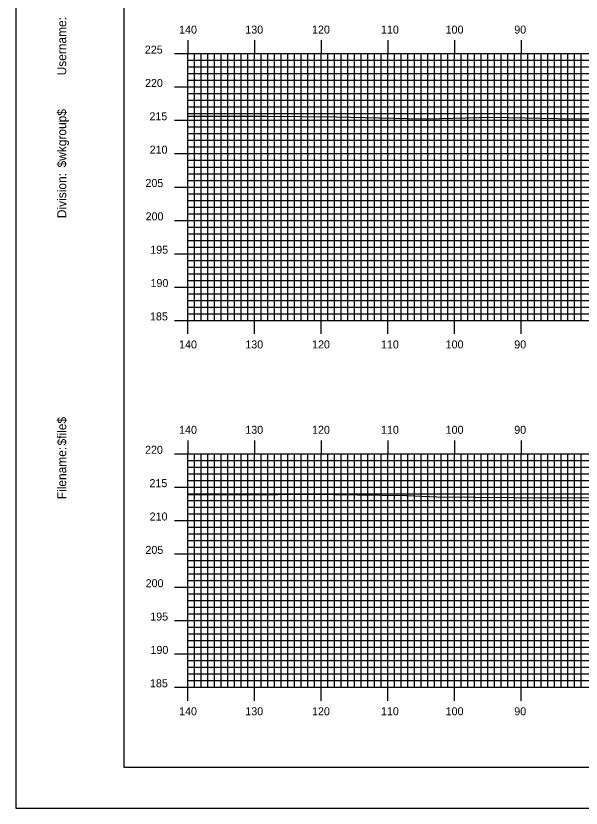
# Model space of a CAD drawing. Extents: x 1800355 to 1800699, y 442591 to 442811.
# Drawn here: x 1800355.2 to 1800440, y 442590.5 to 442709.3 of the extents above; entities that cross this region are included whole.
import ezdxf

# ---------------------------------------------------------------- set-up
doc = ezdxf.new("R2010")
doc.units = 0
for name, color, linetype in [('BORDER', 7, 'Continuous'), ('H_V ANNOTATION', 7, 'Continuous'), ('MAJOR', 7, 'Continuous'), ('MINOR', 7, 'Continuous'), ('PLOT BOUNDARY', 7, 'Continuous'), ('S_Roadway_Centerline', 7, 'Continuous')]:
    doc.layers.add(name, color=color, linetype=linetype)

msp = doc.modelspace()

# ---------------------------------------------------------------- linework, layer by layer
at = {"layer": 'BORDER'}
msp.add_lwpolyline([(1800371.44, 442596.67), (1800691.44, 442596.67), (1800691.44, 442806.67), (1800371.44, 442806.67)], close=True, dxfattribs=at)
at = {"layer": 'MAJOR'}
for p, q in [((1800381.04, 442705.67), (1800381.04, 442703.67)), ((1800391.04, 442705.67), (1800391.04, 442703.67)), ((1800401.04, 442705.67), (1800401.04, 442703.67)), ((1800411.04, 442705.67), (1800411.04, 442703.67)), ((1800421.04, 442705.67), (1800421.04, 442703.67)), ((1800431.04, 442705.67), (1800431.04, 442703.67)), ((1800379.03, 442703.67), (1800381.04, 442703.67)), ((1800381.04, 442703.67), (1800661.04, 442703.67)), ((1800381.04, 442663.67), (1800381.04, 442703.67)), ((1800381.04, 442663.67), (1800381.04, 442703.67)), ((1800381.04, 442703.67), (1800661.04, 442703.67)), ((1800391.04, 442663.67), (1800391.04, 442703.67)), ((1800401.04, 442663.67), (1800401.04, 442703.67)), ((1800411.04, 442663.67), (1800411.04, 442703.67)), ((1800421.04, 442663.67), (1800421.04, 442703.67)), ((1800431.04, 442663.67), (1800431.04, 442703.67)), ((1800379.03, 442698.67), (1800381.04, 442698.67)), ((1800381.04, 442698.67), (1800661.04, 442698.67)), ((1800379.03, 442693.67), (1800381.04, 442693.67)), ((1800381.04, 442693.67), (1800661.04, 442693.67)), ((1800379.03, 442688.67), (1800381.04, 442688.67)), ((1800381.04, 442688.67), (1800661.04, 442688.67)), ((1800379.03, 442683.67), (1800381.04, 442683.67)), ((1800381.04, 442683.67), (1800661.04, 442683.67)), ((1800379.03, 442678.67), (1800381.04, 442678.67)), ((1800381.04, 442678.67), (1800661.04, 442678.67)), ((1800379.03, 442673.67), (1800381.04, 442673.67)), ((1800381.04, 442673.67), (1800661.04, 442673.67)), ((1800379.03, 442668.67), (1800381.04, 442668.67)), ((1800381.04, 442668.67), (1800661.04, 442668.67)), ((1800379.03, 442663.67), (1800381.04, 442663.67)), ((1800381.04, 442663.67), (1800661.04, 442663.67)), ((1800381.04, 442663.67), (1800661.04, 442663.67)), ((1800381.04, 442661.66), (1800381.04, 442663.67)), ((1800391.04, 442661.66), (1800391.04, 442663.67)), ((1800401.04, 442661.66), (1800401.04, 442663.67)), ((1800411.04, 442661.66), (1800411.04, 442663.67)), ((1800421.04, 442661.66), (1800421.04, 442663.67)), ((1800431.04, 442661.66), (1800431.04, 442663.67)), ((1800381.04, 442645.67), (1800381.04, 442643.67)), ((1800391.04, 442645.67), (1800391.04, 442643.67)), ((1800401.04, 442645.67), (1800401.04, 442643.67)), ((1800411.04, 442645.67), (1800411.04, 442643.67)), ((1800421.04, 442645.67), (1800421.04, 442643.67)), ((1800431.04, 442645.67), (1800431.04, 442643.67)), ((1800379.03, 442643.67), (1800381.04, 442643.67)), ((1800381.04, 442643.67), (1800661.04, 442643.67)), ((1800381.04, 442608.67), (1800381.04, 442643.67)), ((1800381.04, 442608.67), (1800381.04, 442643.67)), ((1800381.04, 442643.67), (1800661.04, 442643.67)), ((1800391.04, 442608.67), (1800391.04, 442643.67)), ((1800401.04, 442608.67), (1800401.04, 442643.67)), ((1800411.04, 442608.67), (1800411.04, 442643.67)), ((1800421.04, 442608.67), (1800421.04, 442643.67)), ((1800431.04, 442608.67), (1800431.04, 442643.67)), ((1800379.03, 442638.67), (1800381.04, 442638.67)), ((1800381.04, 442638.67), (1800661.04, 442638.67)), ((1800379.03, 442633.67), (1800381.04, 442633.67)), ((1800381.04, 442633.67), (1800661.04, 442633.67)), ((1800379.03, 442628.67), (1800381.04, 442628.67)), ((1800381.04, 442628.67), (1800661.04, 442628.67)), ((1800379.03, 442623.67), (1800381.04, 442623.67)), ((1800381.04, 442623.67), (1800661.04, 442623.67)), ((1800379.03, 442618.67), (1800381.04, 442618.67)), ((1800381.04, 442618.67), (1800661.04, 442618.67)), ((1800379.03, 442613.67), (1800381.04, 442613.67)), ((1800381.04, 442613.67), (1800661.04, 442613.67)), ((1800379.03, 442608.67), (1800381.04, 442608.67)), ((1800381.04, 442608.67), (1800661.04, 442608.67)), ((1800381.04, 442608.67), (1800661.04, 442608.67)), ((1800381.04, 442606.66), (1800381.04, 442608.67)), ((1800391.04, 442606.66), (1800391.04, 442608.67)), ((1800401.04, 442606.66), (1800401.04, 442608.67)), ((1800411.04, 442606.66), (1800411.04, 442608.67)), ((1800421.04, 442606.66), (1800421.04, 442608.67)), ((1800431.04, 442606.66), (1800431.04, 442608.67))]:
    msp.add_line(p, q, dxfattribs=at)
at = {"layer": 'MINOR'}
for p, q in [((1800381.04, 442702.67), (1800661.04, 442702.67)), ((1800381.04, 442702.67), (1800383.04, 442702.67)), ((1800382.04, 442663.67), (1800382.04, 442703.67)), ((1800383.04, 442663.67), (1800383.04, 442703.67)), ((1800384.04, 442663.67), (1800384.04, 442703.67)), ((1800385.04, 442663.67), (1800385.04, 442703.67)), ((1800386.04, 442663.67), (1800386.04, 442703.67)), ((1800387.04, 442663.67), (1800387.04, 442703.67)), ((1800388.04, 442663.67), (1800388.04, 442703.67)), ((1800389.04, 442663.67), (1800389.04, 442703.67)), ((1800390.04, 442663.67), (1800390.04, 442703.67)), ((1800392.04, 442663.67), (1800392.04, 442703.67)), ((1800393.04, 442663.67), (1800393.04, 442703.67)), ((1800394.04, 442663.67), (1800394.04, 442703.67)), ((1800395.04, 442663.67), (1800395.04, 442703.67)), ((1800396.04, 442663.67), (1800396.04, 442703.67)), ((1800397.04, 442663.67), (1800397.04, 442703.67)), ((1800398.04, 442663.67), (1800398.04, 442703.67)), ((1800399.04, 442663.67), (1800399.04, 442703.67)), ((1800400.04, 442663.67), (1800400.04, 442703.67)), ((1800402.04, 442663.67), (1800402.04, 442703.67)), ((1800403.04, 442663.67), (1800403.04, 442703.67)), ((1800404.04, 442663.67), (1800404.04, 442703.67)), ((1800405.04, 442663.67), (1800405.04, 442703.67)), ((1800406.04, 442663.67), (1800406.04, 442703.67)), ((1800407.04, 442663.67), (1800407.04, 442703.67)), ((1800408.04, 442663.67), (1800408.04, 442703.67)), ((1800409.04, 442663.67), (1800409.04, 442703.67)), ((1800410.04, 442663.67), (1800410.04, 442703.67)), ((1800412.04, 442663.67), (1800412.04, 442703.67)), ((1800413.04, 442663.67), (1800413.04, 442703.67)), ((1800414.04, 442663.67), (1800414.04, 442703.67)), ((1800415.04, 442663.67), (1800415.04, 442703.67)), ((1800416.04, 442663.67), (1800416.04, 442703.67)), ((1800417.04, 442663.67), (1800417.04, 442703.67)), ((1800418.04, 442663.67), (1800418.04, 442703.67)), ((1800419.04, 442663.67), (1800419.04, 442703.67)), ((1800420.04, 442663.67), (1800420.04, 442703.67)), ((1800422.04, 442663.67), (1800422.04, 442703.67)), ((1800423.04, 442663.67), (1800423.04, 442703.67)), ((1800424.04, 442663.67), (1800424.04, 442703.67)), ((1800425.04, 442663.67), (1800425.04, 442703.67)), ((1800426.04, 442663.67), (1800426.04, 442703.67)), ((1800427.04, 442663.67), (1800427.04, 442703.67)), ((1800428.04, 442663.67), (1800428.04, 442703.67)), ((1800429.04, 442663.67), (1800429.04, 442703.67)), ((1800430.04, 442663.67), (1800430.04, 442703.67)), ((1800432.04, 442663.67), (1800432.04, 442703.67)), ((1800433.04, 442663.67), (1800433.04, 442703.67)), ((1800434.04, 442663.67), (1800434.04, 442703.67)), ((1800435.04, 442663.67), (1800435.04, 442703.67)), ((1800436.04, 442663.67), (1800436.04, 442703.67)), ((1800437.04, 442663.67), (1800437.04, 442703.67)), ((1800438.04, 442663.67), (1800438.04, 442703.67)), ((1800439.04, 442663.67), (1800439.04, 442703.67)), ((1800440.04, 442663.67), (1800440.04, 442703.67)), ((1800381.04, 442701.67), (1800661.04, 442701.67)), ((1800381.04, 442701.67), (1800383.04, 442701.67)), ((1800381.04, 442700.67), (1800661.04, 442700.67)), ((1800381.04, 442700.67), (1800383.04, 442700.67)), ((1800381.04, 442699.67), (1800661.04, 442699.67)), ((1800381.04, 442699.67), (1800383.04, 442699.67)), ((1800381.04, 442697.67), (1800661.04, 442697.67)), ((1800381.04, 442697.67), (1800383.04, 442697.67)), ((1800381.04, 442696.67), (1800661.04, 442696.67)), ((1800381.04, 442696.67), (1800383.04, 442696.67)), ((1800381.04, 442695.67), (1800661.04, 442695.67)), ((1800381.04, 442695.67), (1800383.04, 442695.67)), ((1800381.04, 442694.67), (1800661.04, 442694.67)), ((1800381.04, 442694.67), (1800383.04, 442694.67)), ((1800381.04, 442692.67), (1800661.04, 442692.67)), ((1800381.04, 442692.67), (1800383.04, 442692.67)), ((1800381.04, 442691.67), (1800661.04, 442691.67)), ((1800381.04, 442691.67), (1800383.04, 442691.67)), ((1800381.04, 442690.67), (1800661.04, 442690.67)), ((1800381.04, 442690.67), (1800383.04, 442690.67)), ((1800381.04, 442689.67), (1800661.04, 442689.67)), ((1800381.04, 442689.67), (1800383.04, 442689.67)), ((1800381.04, 442687.67), (1800661.04, 442687.67)), ((1800381.04, 442687.67), (1800383.04, 442687.67)), ((1800381.04, 442686.67), (1800661.04, 442686.67)), ((1800381.04, 442686.67), (1800383.04, 442686.67)), ((1800381.04, 442685.67), (1800661.04, 442685.67)), ((1800381.04, 442685.67), (1800383.04, 442685.67)), ((1800381.04, 442684.67), (1800661.04, 442684.67)), ((1800381.04, 442684.67), (1800383.04, 442684.67)), ((1800381.04, 442682.67), (1800661.04, 442682.67)), ((1800381.04, 442682.67), (1800383.04, 442682.67)), ((1800381.04, 442681.67), (1800661.04, 442681.67)), ((1800381.04, 442681.67), (1800383.04, 442681.67)), ((1800381.04, 442680.67), (1800661.04, 442680.67)), ((1800381.04, 442680.67), (1800383.04, 442680.67)), ((1800381.04, 442679.67), (1800661.04, 442679.67)), ((1800381.04, 442679.67), (1800383.04, 442679.67)), ((1800381.04, 442677.67), (1800661.04, 442677.67)), ((1800381.04, 442677.67), (1800383.04, 442677.67)), ((1800381.04, 442676.67), (1800661.04, 442676.67)), ((1800381.04, 442676.67), (1800383.04, 442676.67)), ((1800381.04, 442675.67), (1800661.04, 442675.67)), ((1800381.04, 442675.67), (1800383.04, 442675.67)), ((1800381.04, 442674.67), (1800661.04, 442674.67)), ((1800381.04, 442674.67), (1800383.04, 442674.67)), ((1800381.04, 442672.67), (1800661.04, 442672.67)), ((1800381.04, 442672.67), (1800383.04, 442672.67)), ((1800381.04, 442671.67), (1800661.04, 442671.67)), ((1800381.04, 442671.67), (1800383.04, 442671.67)), ((1800381.04, 442670.67), (1800661.04, 442670.67)), ((1800381.04, 442670.67), (1800383.04, 442670.67)), ((1800381.04, 442669.67), (1800661.04, 442669.67)), ((1800381.04, 442669.67), (1800383.04, 442669.67)), ((1800381.04, 442667.67), (1800661.04, 442667.67)), ((1800381.04, 442667.67), (1800383.04, 442667.67)), ((1800381.04, 442666.67), (1800661.04, 442666.67)), ((1800381.04, 442666.67), (1800383.04, 442666.67)), ((1800381.04, 442665.67), (1800661.04, 442665.67)), ((1800381.04, 442665.67), (1800383.04, 442665.67)), ((1800381.04, 442664.67), (1800661.04, 442664.67)), ((1800381.04, 442664.67), (1800383.04, 442664.67)), ((1800382.04, 442608.67), (1800382.04, 442643.67)), ((1800383.04, 442608.67), (1800383.04, 442643.67)), ((1800384.04, 442608.67), (1800384.04, 442643.67)), ((1800385.04, 442608.67), (1800385.04, 442643.67)), ((1800386.04, 442608.67), (1800386.04, 442643.67)), ((1800387.04, 442608.67), (1800387.04, 442643.67)), ((1800388.04, 442608.67), (1800388.04, 442643.67)), ((1800389.04, 442608.67), (1800389.04, 442643.67)), ((1800390.04, 442608.67), (1800390.04, 442643.67)), ((1800392.04, 442608.67), (1800392.04, 442643.67)), ((1800393.04, 442608.67), (1800393.04, 442643.67)), ((1800394.04, 442608.67), (1800394.04, 442643.67)), ((1800395.04, 442608.67), (1800395.04, 442643.67)), ((1800396.04, 442608.67), (1800396.04, 442643.67)), ((1800397.04, 442608.67), (1800397.04, 442643.67)), ((1800398.04, 442608.67), (1800398.04, 442643.67)), ((1800399.04, 442608.67), (1800399.04, 442643.67)), ((1800400.04, 442608.67), (1800400.04, 442643.67)), ((1800402.04, 442608.67), (1800402.04, 442643.67)), ((1800403.04, 442608.67), (1800403.04, 442643.67)), ((1800404.04, 442608.67), (1800404.04, 442643.67)), ((1800405.04, 442608.67), (1800405.04, 442643.67)), ((1800406.04, 442608.67), (1800406.04, 442643.67)), ((1800407.04, 442608.67), (1800407.04, 442643.67)), ((1800408.04, 442608.67), (1800408.04, 442643.67)), ((1800409.04, 442608.67), (1800409.04, 442643.67)), ((1800410.04, 442608.67), (1800410.04, 442643.67)), ((1800412.04, 442608.67), (1800412.04, 442643.67)), ((1800413.04, 442608.67), (1800413.04, 442643.67)), ((1800414.04, 442608.67), (1800414.04, 442643.67)), ((1800415.04, 442608.67), (1800415.04, 442643.67)), ((1800416.04, 442608.67), (1800416.04, 442643.67)), ((1800417.04, 442608.67), (1800417.04, 442643.67)), ((1800418.04, 442608.67), (1800418.04, 442643.67)), ((1800419.04, 442608.67), (1800419.04, 442643.67)), ((1800420.04, 442608.67), (1800420.04, 442643.67)), ((1800422.04, 442608.67), (1800422.04, 442643.67)), ((1800423.04, 442608.67), (1800423.04, 442643.67)), ((1800424.04, 442608.67), (1800424.04, 442643.67)), ((1800425.04, 442608.67), (1800425.04, 442643.67)), ((1800426.04, 442608.67), (1800426.04, 442643.67)), ((1800427.04, 442608.67), (1800427.04, 442643.67)), ((1800428.04, 442608.67), (1800428.04, 442643.67)), ((1800429.04, 442608.67), (1800429.04, 442643.67)), ((1800430.04, 442608.67), (1800430.04, 442643.67)), ((1800432.04, 442608.67), (1800432.04, 442643.67)), ((1800433.04, 442608.67), (1800433.04, 442643.67)), ((1800434.04, 442608.67), (1800434.04, 442643.67)), ((1800435.04, 442608.67), (1800435.04, 442643.67)), ((1800436.04, 442608.67), (1800436.04, 442643.67)), ((1800437.04, 442608.67), (1800437.04, 442643.67)), ((1800438.04, 442608.67), (1800438.04, 442643.67)), ((1800439.04, 442608.67), (1800439.04, 442643.67)), ((1800440.04, 442608.67), (1800440.04, 442643.67)), ((1800381.04, 442642.67), (1800661.04, 442642.67)), ((1800381.04, 442642.67), (1800383.04, 442642.67)), ((1800381.04, 442641.67), (1800661.04, 442641.67)), ((1800381.04, 442641.67), (1800383.04, 442641.67)), ((1800381.04, 442640.67), (1800661.04, 442640.67)), ((1800381.04, 442640.67), (1800383.04, 442640.67)), ((1800381.04, 442639.67), (1800661.04, 442639.67)), ((1800381.04, 442639.67), (1800383.04, 442639.67)), ((1800381.04, 442637.67), (1800661.04, 442637.67)), ((1800381.04, 442637.67), (1800383.04, 442637.67)), ((1800381.04, 442636.67), (1800661.04, 442636.67)), ((1800381.04, 442636.67), (1800383.04, 442636.67)), ((1800381.04, 442635.67), (1800661.04, 442635.67)), ((1800381.04, 442635.67), (1800383.04, 442635.67)), ((1800381.04, 442634.67), (1800661.04, 442634.67)), ((1800381.04, 442634.67), (1800383.04, 442634.67)), ((1800381.04, 442632.67), (1800661.04, 442632.67)), ((1800381.04, 442632.67), (1800383.04, 442632.67)), ((1800381.04, 442631.67), (1800661.04, 442631.67)), ((1800381.04, 442631.67), (1800383.04, 442631.67)), ((1800381.04, 442630.67), (1800661.04, 442630.67)), ((1800381.04, 442630.67), (1800383.04, 442630.67)), ((1800381.04, 442629.67), (1800661.04, 442629.67)), ((1800381.04, 442629.67), (1800383.04, 442629.67)), ((1800381.04, 442627.67), (1800661.04, 442627.67)), ((1800381.04, 442627.67), (1800383.04, 442627.67)), ((1800381.04, 442626.67), (1800661.04, 442626.67)), ((1800381.04, 442626.67), (1800383.04, 442626.67)), ((1800381.04, 442625.67), (1800661.04, 442625.67)), ((1800381.04, 442625.67), (1800383.04, 442625.67)), ((1800381.04, 442624.67), (1800661.04, 442624.67)), ((1800381.04, 442624.67), (1800383.04, 442624.67)), ((1800381.04, 442622.67), (1800661.04, 442622.67)), ((1800381.04, 442622.67), (1800383.04, 442622.67)), ((1800381.04, 442621.67), (1800661.04, 442621.67)), ((1800381.04, 442621.67), (1800383.04, 442621.67)), ((1800381.04, 442620.67), (1800661.04, 442620.67)), ((1800381.04, 442620.67), (1800383.04, 442620.67)), ((1800381.04, 442619.67), (1800661.04, 442619.67)), ((1800381.04, 442619.67), (1800383.04, 442619.67)), ((1800381.04, 442617.67), (1800661.04, 442617.67)), ((1800381.04, 442617.67), (1800383.04, 442617.67)), ((1800381.04, 442616.67), (1800661.04, 442616.67)), ((1800381.04, 442616.67), (1800383.04, 442616.67)), ((1800381.04, 442615.67), (1800661.04, 442615.67)), ((1800381.04, 442615.67), (1800383.04, 442615.67)), ((1800381.04, 442614.67), (1800661.04, 442614.67)), ((1800381.04, 442614.67), (1800383.04, 442614.67)), ((1800381.04, 442612.67), (1800661.04, 442612.67)), ((1800381.04, 442612.67), (1800383.04, 442612.67)), ((1800381.04, 442611.67), (1800661.04, 442611.67)), ((1800381.04, 442611.67), (1800383.04, 442611.67)), ((1800381.04, 442610.67), (1800661.04, 442610.67)), ((1800381.04, 442610.67), (1800383.04, 442610.67)), ((1800381.04, 442609.67), (1800661.04, 442609.67)), ((1800381.04, 442609.67), (1800383.04, 442609.67))]:
    msp.add_line(p, q, dxfattribs=at)
at = {"layer": 'PLOT BOUNDARY'}
msp.add_lwpolyline([(1800355.25, 442590.55), (1800695.25, 442590.55), (1800695.25, 442810.55), (1800355.25, 442810.55)], close=True, dxfattribs=at)
at = {"layer": 'S_Roadway_Centerline'}
for points in [[(1800381.04, 442694.3), (1800390.97, 442694.3), (1800392.78, 442694.3), (1800403.36, 442694.17), (1800414.11, 442693.93), (1800416.85, 442693.88), (1800426.69, 442694.15), (1800436.57, 442693.94), (1800454.39, 442693.87)], [(1800381.04, 442637.58), (1800384.71, 442637.57), (1800390.59, 442637.59), (1800394.62, 442637.58), (1800399.16, 442637.61), (1800413.83, 442637.41), (1800418.38, 442637.2), (1800435.83, 442637.08), (1800456.92, 442637.13), (1800464, 442637.33), (1800472.3, 442637.35), (1800488.2, 442637.4), (1800495.71, 442637.84), (1800501.91, 442637.88), (1800511.04, 442637.36), (1800520.11, 442637.45), (1800523.46, 442637.46), (1800533.83, 442637.49), (1800544.8, 442637.36), (1800557.05, 442637.45), (1800568.72, 442637.52), (1800571.52, 442637.59), (1800590.67, 442637.52)]]:
    msp.add_lwpolyline(points, dxfattribs=at)

# ---------------------------------------------------------------- texts
at = {"layer": 'BORDER'}
for s, p in [('Username:', (1800362.81, 442700.4)), ('$wkgroup$', (1800362.81, 442686.6)), ('Division:', (1800362.81, 442679)), ('$file$', (1800362.81, 442644.92)), ('Filename:', (1800362.81, 442636.86))]:
    msp.add_text(s, height=1.339, rotation=90, dxfattribs=at).set_placement(p)
at = {"layer": 'H_V ANNOTATION'}
for s, p in [('140', (1800379.74, 442706.67)), ('130', (1800389.67, 442706.67)), ('120', (1800399.68, 442706.67)), ('110', (1800410.02, 442706.67)), ('100', (1800419.72, 442706.67)), ('90', (1800430.01, 442706.67)), ('225', (1800374.6, 442703.67)), ('220', (1800374.63, 442698.67)), ('215', (1800375.29, 442693.67)), ('210', (1800375.32, 442688.67)), ('205', (1800374.69, 442683.67)), ('200', (1800374.72, 442678.67)), ('195', (1800375.41, 442673.67)), ('190', (1800375.45, 442668.67)), ('185', (1800375.37, 442663.67)), ('140', (1800379.74, 442659.47)), ('130', (1800389.67, 442659.47)), ('120', (1800399.68, 442659.47)), ('110', (1800410.02, 442659.47)), ('100', (1800419.72, 442659.47)), ('90', (1800430.01, 442659.47)), ('140', (1800379.74, 442646.67)), ('130', (1800389.67, 442646.67)), ('120', (1800399.68, 442646.67)), ('110', (1800410.02, 442646.67)), ('100', (1800419.72, 442646.67)), ('90', (1800430.01, 442646.67)), ('220', (1800374.63, 442643.67)), ('215', (1800375.29, 442638.67)), ('210', (1800375.32, 442633.67)), ('205', (1800374.69, 442628.67)), ('200', (1800374.72, 442623.67)), ('195', (1800375.41, 442618.67)), ('190', (1800375.45, 442613.67)), ('185', (1800375.37, 442608.67)), ('140', (1800379.74, 442604.47)), ('130', (1800389.67, 442604.47)), ('120', (1800399.68, 442604.47)), ('110', (1800410.02, 442604.47)), ('100', (1800419.72, 442604.47)), ('90', (1800430.01, 442604.47))]:
    msp.add_text(s, height=1.2, dxfattribs=at).set_placement(p)
at = {"layer": 'MAJOR'}
for p in [(1800381.03, 442663.67), (1800381.03, 442608.67)]:
    msp.add_text('-', height=0.012, dxfattribs=at).set_placement(p)

doc.saveas('drawing.dxf')
